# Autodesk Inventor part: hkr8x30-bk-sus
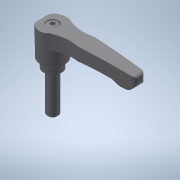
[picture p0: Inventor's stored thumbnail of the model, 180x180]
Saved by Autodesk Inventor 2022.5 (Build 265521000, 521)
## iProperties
Created: 2017-09
Part Number: hkr8x30-bk-sus
Material: 一般
Document SubType Name: Modeling
Designer: imaocorp
Density: 1 g/cm^3
Appearance: 既定
Author: imaocorp
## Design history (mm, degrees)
node "hkr8x30-bk-sus.x_t1"
node "hkr8x30-bk-sus"
node "Base1"
